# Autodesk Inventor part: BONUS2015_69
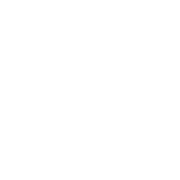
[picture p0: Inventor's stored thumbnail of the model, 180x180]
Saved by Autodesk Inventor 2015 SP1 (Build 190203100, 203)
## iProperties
Created: 2015-05
Part Number: BONUS2015_69
Material: Generisch
Document SubType Name: Modeling
Density: 1 g/cm^3
Appearance: Vorgabe
xx: 69
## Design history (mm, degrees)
